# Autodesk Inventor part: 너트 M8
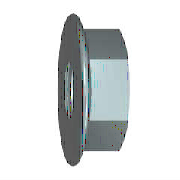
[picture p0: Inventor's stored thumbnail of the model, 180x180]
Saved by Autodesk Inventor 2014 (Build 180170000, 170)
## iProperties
Created: 2015-09
Part Number: 너트 M8
Material: 스테인리스강
Description: 플랜지붙이 6각 너트 - 일반 스레드
Document SubType Name: Modeling
Standard: ISO 4161
Designer: mduedu
Standard Revision: 2판 1999-03-15
Standards Organization: ISO
Language: ko-KR
Size Designation: M8
Categories: <MemberInstance><Categories><Category DisplayName="조임쇠" InternalName="e4da775c-781d-43d5-af7c-5136215cf5a6" Mnemonic="FSTN"><Category DisplayName="너트" InternalN
Density: 8.08 g/cm^3
Appearance: Default
Author: mduedu
IsCustomPart: 1
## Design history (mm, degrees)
sketch "스케치1"
  geometry: L1 (-1.844, 0)-(9.641, 0) reference; L2 (3.107, 6.5)-(2.288, 8.257); L3 (3.107, 6.5)-(8, 6.5); L4 (8, 6.5)-(8, 0); L5 (3.107, 6.5)-(3.107, 0); L6 (0, -1.835)-(0, 11.01) reference; A1 r 1.2 centre (1.2, 7.75) between (2.288, 8.257) and (0, 7.75); 1 further point
  constraints: 8 end point, 3 point on line, 2 perpendicular, 2 point on circle, 2 tangent, 1 centre point, 1 parallel
  dimensions: "d2" = 13 diameter of L3 L1 (= SW); "d4" = 17.9 dimension on A1 L1 (= LADI); "d5" = 1.2 radius of A1 (= PHH); "d15" = 8 distance between parallel lines of L4 L6 (= KOH); "d16" = 25 deg angle of L6 L2 (= KEWI)
revolve "링" sketch "스케치1" stored, may be unused: angle "d8" = 90 deg
sketch "스케치2"
  geometry: L1 (-6.5, -3.753)-(-6.5, 3.753); L2 (-6.5, 3.753)-(0, 7.506); L3 (0, 7.506)-(6.5, 3.753); L4 (6.5, 3.753)-(6.5, -3.753); L5 (6.5, -3.753)-(0, -7.506); L6 (0, -7.506)-(-6.5, -3.753); C1 r 4.9 at (0, 0); C2 r 7.75 at (0, 0) reference; 1 further point
  constraints: 12 end point, 1 centre point, 1 coincident, 1 vertical, 11 other
  dimensions: "d6" = 15.01111 distance of L5.end L2.end (= 1.1547 x SW)
extrude "본체" join sketch "스케치2" distance "d7" = 8 (= KOH); taper "d9" = 0 deg
sketch "스케치3"
  geometry: L1 (2.638, 7.506)-(8, 7.506) reference; L2 (8, 3.753)-(8, 7.506) reference; L3 (0, -7.75)-(0, 7.75) reference; L4 (-1.6, 0)-(9.6, 0) reference; L5 (7.419, 7.506)-(8, 6.5)
  constraints: 2 end point, 2 point on line
  dimensions: "d10" = 30 deg angle of L2 L5 (= ANG1); "d11" = 13 diameter of L5.end L4 (= SW0)
revolve "모따기1" sketch "스케치3" stored, may be unused: angle "d24" = 90 deg
sketch "스케치4"
  geometry: C1 r 7.75 at (0, 0) reference; 1 further point
  constraints: 1 coincident
hole "스레드" sketch "스케치4" at (0, 0) diameter "d25" = 6.647; stored, may be unused: countersink angle "d29" = 82 deg, drill point angle "d31" = 118 deg; dims "d26" = 6, "d27" = 4, "d28" = 2, "d30" = 8
workaxis "Work Axis1"
workplane "Work Plane1"
body "Solid1"
chamfer "모따기2" distance "d12" = 0.67658 (= -0.5 x GD1 + 0.5 x NND); stored, may be unused: angle "d13" = 30 deg, second distance "d46" = 0.67658 (= -0.5 x GD1 + 0.5 x NND)
chamfer "모따기3" distance "d51" = 0.67658 (= -0.5 x GD1 + 0.5 x NND); stored, may be unused: second distance "d52" = 2, angle "d53" = 45 deg
other parameters: "ANG1" = 30 deg [user parameter; used in 1 equation term], "KEWI" = 25 deg [user parameter; used in 1 equation term], "NND" = 8 [user parameter; used in 4 equation terms], "LADI" = 17.9 [user parameter; used in 2 equation terms], "SW" = 13 [user parameter; used in 3 equation terms], "PHH" = 1.2 [user parameter; used in 3 equation terms], "KOH" = 8 (= NND) [user parameter; used in 2 equation terms], "SW0" = 13 [user parameter; used in 1 equation term], "GD1" = 6.64684 (computed from THREADDIA, PTC, TOA) [user parameter; used in 3 equation terms], "d1" = 17.9 (= LADI), "d3" = 1.2 (= PHH), "d45" = 0, "d47" = 0, "d49" = 0, "d54" = 0, "GUL" = 0.67658 (= 0.541266 x PTC) [user parameter], "TPU" = 8 (computed from PTC) [user parameter], "RR" = 1.2 (= PHH) [user parameter], "THREADDIA" = 8 [user parameter; used in 1 equation term], "TOA" = 30 deg [user parameter; used in 1 equation term], "PTC" = 1.25 [user parameter; used in 4 equation terms], "GAL" = 0.67658 (= 0.541266 x PTC) [user parameter], "E0" = 15.015 (= 1.155 x SW) [user parameter]
